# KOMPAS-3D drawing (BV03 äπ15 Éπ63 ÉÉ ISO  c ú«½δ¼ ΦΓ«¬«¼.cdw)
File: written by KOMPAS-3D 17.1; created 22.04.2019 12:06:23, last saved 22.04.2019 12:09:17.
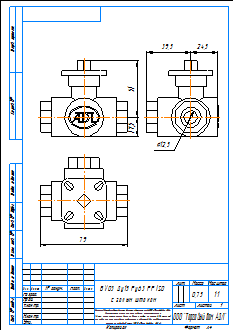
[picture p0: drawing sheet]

Sheet 1: A4, portrait

Title block, sheet 1: name: BV03 Ду15 Ру63 РР ISO / c голым штоком; material: Внимание! Данный продукт является объектом авторского права ООО «Торговый Дом АДЛ». / Запрещается изменение, копирование, распространение / (в том числе путем копирования на другие сайты и ресурсы в Интернете) / или любое иное использование информации и объектов без предварительного / согласия правообладателя (ООО «Торговый Дом АДЛ»).; mass: 0,75; sheets: 1; organisation: ООО "Торговый дом АДЛ"; sheet format: A4

Views: Вид 1, Проекционный вид 2, Проекционный вид 3
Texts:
  user
Dimensions and other numbers on the sheet: 51; 17,5; 24,5; 39,5; 12,5; 79; 1:1; 1; 0,75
